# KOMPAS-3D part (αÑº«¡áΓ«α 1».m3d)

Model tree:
1. Эскиз:1
2. Операция выдавливания:1
     Толщина стенки 1 = 2; Толщина стенки 2 = 8; Расстояние 1 = 1
3. Эскиз:3
4. Операция выдавливания:2
     Толщина стенки 1 = 2; Толщина стенки 2 = 6; Расстояние 1 = 5.5
5. Эскиз:4
6. Операция выдавливания:3
     Толщина стенки 1 = 2; Толщина стенки 2 = 6; Расстояние 1 = 1
7. Эскиз:5
8. Эскиз:6
9. Операция выдавливания:4
     Толщина стенки 1 = 2; Толщина стенки 2 = 2.5; Расстояние 1 = 50
10. Эскиз:7
11. Вырезать элемент выдавливания:1
     Толщина стенки 2 = 1.5; Расстояние 1 = 40
12. Эскиз:8
13. Операция выдавливания:5
     Толщина стенки 1 = 2; Толщина стенки 2 = 2.5; Расстояние 1 = 50
14. Эскиз:9
15. Вырезать элемент выдавливания:2
     Толщина стенки 2 = 1.5; Расстояние 1 = 40
16. Эскиз:10
17. Операция выдавливания:6
     Толщина стенки 1 = 2; Толщина стенки 2 = 2.5; Расстояние 1 = 10
18. Эскиз:11
19. Операция выдавливания:7
     Толщина стенки 1 = 2; Толщина стенки 2 = 6; Расстояние 1 = 1
20. Эскиз:12
21. Операция выдавливания:8
     Толщина стенки 1 = 2; Толщина стенки 2 = 6; Расстояние 1 = 5.5
22. Эскиз:13
23. Операция выдавливания:9
     Толщина стенки 1 = 2; Толщина стенки 2 = 8; Расстояние 1 = 1
24. Эскиз:14
25. Вырезать элемент выдавливания:3
     Толщина стенки 2 = 1.5; Расстояние 1 = 23
26. Эскиз:15
27. Вырезать элемент выдавливания:4
     Толщина стенки 2 = 1.5; Расстояние 1 = 1
28. Эскиз:16
29. Вырезать элемент выдавливания:5
     Расстояние 1 = 150
30. Эскиз:17
31. Операция выдавливания:10
     Толщина стенки 1 = 8; Толщина стенки 2 = 8; Расстояние 1 = 10; Расстояние 2 = 0.4
